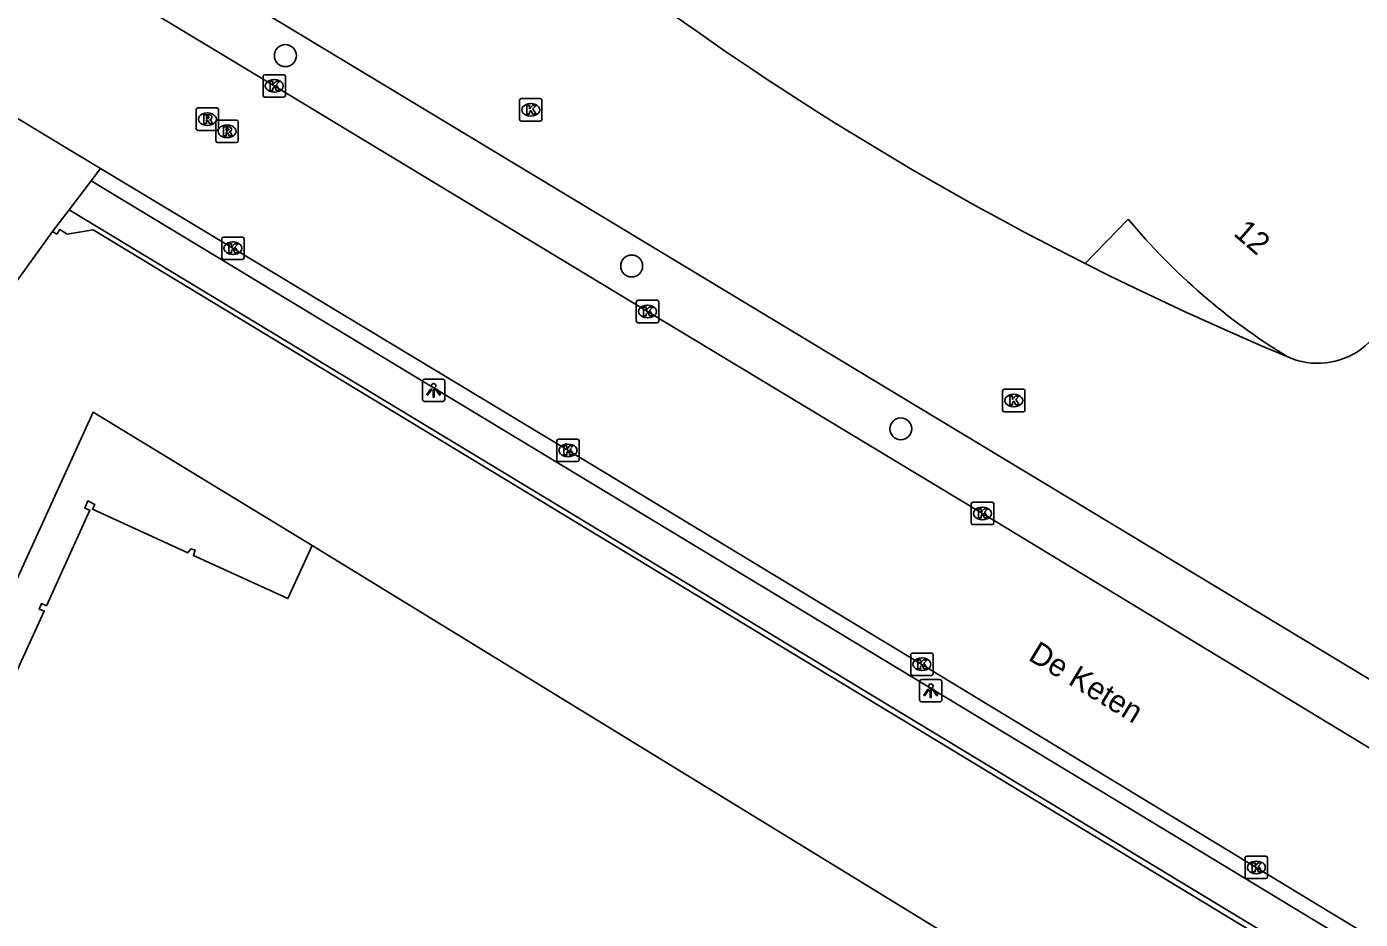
# Model space of a CAD drawing. Extents: x 156141 to 158132, y 385651 to 388399.
# Drawn here: x 156406.3 to 156465.9, y 386691.9 to 386731.7 of the extents above; entities that cross this region are included whole.
import ezdxf

# ---------------------------------------------------------------- set-up
doc = ezdxf.new("R2010")
doc.units = 0
for name, color, linetype in [('IMGEO_Berm_groen', 7, 'Continuous'), ('IMGEO_Boom', 7, 'Continuous'), ('IMGEO_Groenvoorziening', 7, 'Continuous'), ('IMGEO_Hek', 7, 'Continuous'), ('IMGEO_Kolk', 7, 'Continuous'), ('IMGEO_Lichtpunt', 7, 'Continuous'), ('IMGEO_Openbare_ruimte_label', 7, 'Continuous'), ('IMGEO_Pand', 7, 'Continuous'), ('IMGEO_Pand_nummerreeks', 7, 'Continuous'), ('IMGEO_Pand_overbouw', 7, 'Continuous'), ('IMGEO_Rijbaan_lokaal_gesloten', 7, 'Continuous'), ('IMGEO_Rijbaan_lokaal_open', 7, 'Continuous'), ('IMGEO_Rioolput', 7, 'Continuous'), ('IMGEO_Voetpad_open', 7, 'Continuous')]:
    doc.layers.add(name, color=color, linetype=linetype)

msp = doc.modelspace()

# ---------------------------------------------------------------- linework, layer by layer
at = {"layer": 'IMGEO_Berm_groen'}
msp.add_lwpolyline([(156478.507, 386695.242), (156416.672, 386732.53)], dxfattribs=at)
at = {"layer": 'IMGEO_Boom'}
for centre in [(156417.896, 386730.437), (156433.358, 386721.045), (156445.376, 386713.777)]:
    msp.add_circle(centre, 0.489, dxfattribs=at)
at = {"layer": 'IMGEO_Groenvoorziening'}
msp.add_lwpolyline([(156503.694, 386665.403), (156495.572, 386670.446), (156409.308, 386722.659), (156408.147, 386722.464), (156407.83, 386722.679), (156407.689, 386722.471), (156407.499, 386722.585)], dxfattribs=at)
at = {"layer": 'IMGEO_Hek'}
msp.add_lwpolyline([(156416.672, 386732.53), (156478.507, 386695.242)], dxfattribs=at)
at = {"layer": 'IMGEO_Kolk'}
for p, q in [((156416.899, 386728.659), (156416.899, 386729.511)), ((156416.974, 386729.585), (156417.826, 386729.585)), ((156417.387, 386729.365), (156417.412, 386729.365)), ((156417.9, 386729.511), (156417.9, 386728.659)), ((156417.41, 386728.805), (156417.385, 386728.805)), ((156417.826, 386728.585), (156416.974, 386728.585)), ((156428.352, 386727.59), (156428.352, 386728.442)), ((156428.427, 386728.516), (156429.279, 386728.516)), ((156428.84, 386728.296), (156428.865, 386728.296)), ((156429.353, 386728.442), (156429.353, 386727.59)), ((156429.279, 386727.516), (156428.427, 386727.516)), ((156428.863, 386727.736), (156428.838, 386727.736)), ((156415.051, 386721.413), (156415.051, 386722.265)), ((156415.126, 386722.339), (156415.978, 386722.339)), ((156415.539, 386722.119), (156415.564, 386722.119)), ((156416.052, 386722.265), (156416.052, 386721.413)), ((156415.562, 386721.559), (156415.537, 386721.559)), ((156415.978, 386721.339), (156415.126, 386721.339)), ((156433.567, 386718.589), (156433.567, 386719.441)), ((156433.642, 386719.515), (156434.494, 386719.515)), ((156434.055, 386719.295), (156434.08, 386719.295)), ((156434.568, 386719.441), (156434.568, 386718.589)), ((156434.494, 386718.515), (156433.642, 386718.515)), ((156434.078, 386718.735), (156434.053, 386718.735)), ((156449.997, 386715.541), (156450.849, 386715.541)), ((156449.922, 386714.615), (156449.922, 386715.467)), ((156450.41, 386715.321), (156450.435, 386715.321)), ((156450.923, 386715.467), (156450.923, 386714.615)), ((156450.849, 386714.541), (156449.997, 386714.541)), ((156450.433, 386714.761), (156450.408, 386714.761)), ((156430.015, 386712.389), (156430.015, 386713.241)), ((156430.09, 386713.315), (156430.942, 386713.315)), ((156431.016, 386713.241), (156431.016, 386712.389)), ((156430.526, 386712.535), (156430.501, 386712.535)), ((156430.503, 386713.095), (156430.528, 386713.095)), ((156430.942, 386712.315), (156430.09, 386712.315)), ((156448.524, 386709.575), (156448.524, 386710.427)), ((156448.599, 386710.501), (156449.451, 386710.501)), ((156449.012, 386710.281), (156449.037, 386710.281)), ((156449.525, 386710.427), (156449.525, 386709.575)), ((156449.035, 386709.721), (156449.01, 386709.721)), ((156449.451, 386709.501), (156448.599, 386709.501)), ((156445.818, 386702.843), (156445.818, 386703.695)), ((156445.893, 386703.769), (156446.745, 386703.769)), ((156446.819, 386703.695), (156446.819, 386702.843)), ((156446.329, 386702.989), (156446.304, 386702.989)), ((156446.306, 386703.549), (156446.331, 386703.549)), ((156446.745, 386702.769), (156445.893, 386702.769)), ((156460.828, 386694.7), (156461.68, 386694.7)), ((156460.753, 386693.774), (156460.753, 386694.626)), ((156461.241, 386694.48), (156461.266, 386694.48)), ((156461.754, 386694.626), (156461.754, 386693.774)), ((156461.68, 386693.7), (156460.828, 386693.7)), ((156461.264, 386693.92), (156461.239, 386693.92))]:
    msp.add_line(p, q, dxfattribs=at)
for points in [[(156416.899, 386728.659), (156416.899, 386729.511)], [(156416.974, 386729.585), (156417.826, 386729.585)], [(156417.22, 386729.285), (156417.343, 386729.285), (156417.343, 386729.134), (156417.473, 386729.285), (156417.637, 386729.285), (156417.491, 386729.134), (156417.644, 386728.885), (156417.492, 386728.885), (156417.407, 386729.049), (156417.343, 386728.982), (156417.343, 386728.885), (156417.22, 386728.885), (156417.22, 386729.285)], [(156417.9, 386729.511), (156417.9, 386728.659)], [(156417.826, 386728.585), (156416.974, 386728.585)], [(156428.352, 386727.59), (156428.352, 386728.442)], [(156428.427, 386728.516), (156429.279, 386728.516)], [(156428.673, 386728.216), (156428.796, 386728.216), (156428.796, 386728.065), (156428.926, 386728.216), (156429.09, 386728.216), (156428.944, 386728.065), (156429.097, 386727.816), (156428.945, 386727.816), (156428.86, 386727.98), (156428.796, 386727.913), (156428.796, 386727.816), (156428.673, 386727.816), (156428.673, 386728.216)], [(156429.353, 386728.442), (156429.353, 386727.59)], [(156429.279, 386727.516), (156428.427, 386727.516)], [(156415.051, 386721.413), (156415.051, 386722.265)], [(156415.126, 386722.339), (156415.978, 386722.339)], [(156416.052, 386722.265), (156416.052, 386721.413)], [(156415.372, 386722.039), (156415.495, 386722.039), (156415.495, 386721.888), (156415.625, 386722.039), (156415.789, 386722.039), (156415.643, 386721.888), (156415.796, 386721.639), (156415.644, 386721.639), (156415.559, 386721.803), (156415.495, 386721.736), (156415.495, 386721.639), (156415.372, 386721.639), (156415.372, 386722.039)], [(156415.978, 386721.339), (156415.126, 386721.339)], [(156433.567, 386718.589), (156433.567, 386719.441)], [(156433.642, 386719.515), (156434.494, 386719.515)], [(156433.888, 386719.215), (156434.011, 386719.215), (156434.011, 386719.064), (156434.141, 386719.215), (156434.305, 386719.215), (156434.159, 386719.064), (156434.312, 386718.815), (156434.16, 386718.815), (156434.075, 386718.979), (156434.011, 386718.912), (156434.011, 386718.815), (156433.888, 386718.815), (156433.888, 386719.215)], [(156434.568, 386719.441), (156434.568, 386718.589)], [(156434.494, 386718.515), (156433.642, 386718.515)], [(156449.997, 386715.541), (156450.849, 386715.541)], [(156449.922, 386714.615), (156449.922, 386715.467)], [(156450.243, 386715.241), (156450.366, 386715.241), (156450.366, 386715.09), (156450.496, 386715.241), (156450.66, 386715.241), (156450.514, 386715.09), (156450.667, 386714.841), (156450.515, 386714.841), (156450.43, 386715.005), (156450.366, 386714.938), (156450.366, 386714.841), (156450.243, 386714.841), (156450.243, 386715.241)], [(156450.923, 386715.467), (156450.923, 386714.615)], [(156450.849, 386714.541), (156449.997, 386714.541)], [(156430.015, 386712.389), (156430.015, 386713.241)], [(156430.09, 386713.315), (156430.942, 386713.315)], [(156431.016, 386713.241), (156431.016, 386712.389)], [(156430.336, 386713.015), (156430.459, 386713.015), (156430.459, 386712.864), (156430.589, 386713.015), (156430.753, 386713.015), (156430.607, 386712.864), (156430.76, 386712.615), (156430.608, 386712.615), (156430.523, 386712.779), (156430.459, 386712.712), (156430.459, 386712.615), (156430.336, 386712.615), (156430.336, 386713.015)], [(156430.942, 386712.315), (156430.09, 386712.315)], [(156448.524, 386709.575), (156448.524, 386710.427)], [(156448.599, 386710.501), (156449.451, 386710.501)], [(156448.845, 386710.201), (156448.968, 386710.201), (156448.968, 386710.05), (156449.098, 386710.201), (156449.262, 386710.201), (156449.116, 386710.05), (156449.269, 386709.801), (156449.117, 386709.801), (156449.032, 386709.965), (156448.968, 386709.898), (156448.968, 386709.801), (156448.845, 386709.801), (156448.845, 386710.201)], [(156449.525, 386710.427), (156449.525, 386709.575)], [(156449.451, 386709.501), (156448.599, 386709.501)], [(156445.818, 386702.843), (156445.818, 386703.695)], [(156445.893, 386703.769), (156446.745, 386703.769)], [(156446.819, 386703.695), (156446.819, 386702.843)], [(156446.139, 386703.469), (156446.262, 386703.469), (156446.262, 386703.318), (156446.392, 386703.469), (156446.556, 386703.469), (156446.41, 386703.318), (156446.563, 386703.069), (156446.411, 386703.069), (156446.326, 386703.233), (156446.262, 386703.166), (156446.262, 386703.069), (156446.139, 386703.069), (156446.139, 386703.469)], [(156446.745, 386702.769), (156445.893, 386702.769)], [(156460.828, 386694.7), (156461.68, 386694.7)], [(156460.753, 386693.774), (156460.753, 386694.626)], [(156461.074, 386694.4), (156461.197, 386694.4), (156461.197, 386694.249), (156461.327, 386694.4), (156461.491, 386694.4), (156461.345, 386694.249), (156461.498, 386694), (156461.346, 386694), (156461.261, 386694.164), (156461.197, 386694.097), (156461.197, 386694), (156461.074, 386694), (156461.074, 386694.4)], [(156461.754, 386694.626), (156461.754, 386693.774)], [(156461.68, 386693.7), (156460.828, 386693.7)]]:
    msp.add_lwpolyline(points, dxfattribs=at)
for centre, start, end in [((156416.976, 386729.509), 91.55205, 178.44795), ((156416.976, 386729.509), 91.55205, 178.44795), ((156417.824, 386729.509), 1.55205, 88.44795), ((156417.824, 386729.509), 1.55205, 88.44795), ((156416.976, 386728.661), 181.55205, 268.44795), ((156416.976, 386728.661), 181.55205, 268.44795), ((156417.824, 386728.661), 271.55205, 358.44795), ((156417.824, 386728.661), 271.55205, 358.44795), ((156428.429, 386728.44), 91.55205, 178.44795), ((156428.429, 386728.44), 91.55205, 178.44795), ((156429.277, 386728.44), 1.55205, 88.44795), ((156429.277, 386728.44), 1.55205, 88.44795), ((156428.429, 386727.592), 181.55205, 268.44795), ((156428.429, 386727.592), 181.55205, 268.44795), ((156429.277, 386727.592), 271.55205, 358.44795), ((156429.277, 386727.592), 271.55205, 358.44795), ((156415.128, 386722.263), 91.55205, 178.44795), ((156415.128, 386722.263), 91.55205, 178.44795), ((156415.976, 386722.263), 1.55205, 88.44795), ((156415.976, 386722.263), 1.55205, 88.44795), ((156415.128, 386721.415), 181.55205, 268.44795), ((156415.128, 386721.415), 181.55205, 268.44795), ((156415.976, 386721.415), 271.55205, 358.44795), ((156415.976, 386721.415), 271.55205, 358.44795), ((156433.644, 386719.439), 91.55205, 178.44795), ((156433.644, 386719.439), 91.55205, 178.44795), ((156434.492, 386719.439), 1.55205, 88.44795), ((156434.492, 386719.439), 1.55205, 88.44795), ((156433.644, 386718.591), 181.55205, 268.44795), ((156433.644, 386718.591), 181.55205, 268.44795), ((156434.492, 386718.591), 271.55205, 358.44795), ((156434.492, 386718.591), 271.55205, 358.44795), ((156449.999, 386715.465), 91.55205, 178.44795), ((156449.999, 386715.465), 91.55205, 178.44795), ((156450.847, 386715.465), 1.55205, 88.44795), ((156450.847, 386715.465), 1.55205, 88.44795), ((156449.999, 386714.617), 181.55205, 268.44795), ((156449.999, 386714.617), 181.55205, 268.44795), ((156450.847, 386714.617), 271.55205, 358.44795), ((156450.847, 386714.617), 271.55205, 358.44795), ((156430.092, 386713.239), 91.55205, 178.44795), ((156430.092, 386713.239), 91.55205, 178.44795), ((156430.94, 386713.239), 1.55205, 88.44795), ((156430.94, 386713.239), 1.55205, 88.44795), ((156430.092, 386712.391), 181.55205, 268.44795), ((156430.092, 386712.391), 181.55205, 268.44795), ((156430.94, 386712.391), 271.55205, 358.44795), ((156430.94, 386712.391), 271.55205, 358.44795), ((156448.601, 386710.425), 91.55205, 178.44795), ((156448.601, 386710.425), 91.55205, 178.44795), ((156449.449, 386710.425), 1.55205, 88.44795), ((156449.449, 386710.425), 1.55205, 88.44795), ((156448.601, 386709.577), 181.55205, 268.44795), ((156448.601, 386709.577), 181.55205, 268.44795), ((156449.449, 386709.577), 271.55205, 358.44795), ((156449.449, 386709.577), 271.55205, 358.44795), ((156445.895, 386703.693), 91.55205, 178.44795), ((156445.895, 386703.693), 91.55205, 178.44795), ((156446.743, 386703.693), 1.55205, 88.44795), ((156446.743, 386703.693), 1.55205, 88.44795), ((156445.895, 386702.845), 181.55205, 268.44795), ((156445.895, 386702.845), 181.55205, 268.44795), ((156446.743, 386702.845), 271.55205, 358.44795), ((156446.743, 386702.845), 271.55205, 358.44795), ((156460.83, 386694.624), 91.55205, 178.44795), ((156460.83, 386694.624), 91.55205, 178.44795), ((156461.678, 386694.624), 1.55205, 88.44795), ((156461.678, 386694.624), 1.55205, 88.44795), ((156460.83, 386693.776), 181.55205, 268.44795), ((156460.83, 386693.776), 181.55205, 268.44795), ((156461.678, 386693.776), 271.55205, 358.44795), ((156461.678, 386693.776), 271.55205, 358.44795)]:
    msp.add_arc(centre, 0.0765, start, end, dxfattribs=at)
for centre, major_axis, ratio, start_param, end_param in [((156417.386, 386729.085), (-0.387, 0.002), 0.722429, 4.712389, 7.853982), ((156417.411, 386729.085), (-0.39, 0.002), 0.717154, 1.570796, 4.712389), ((156428.839, 386728.016), (-0.387, 0.002), 0.722429, 4.712389, 7.853982), ((156428.864, 386728.016), (-0.39, 0.002), 0.717154, 1.570796, 4.712389), ((156415.538, 386721.839), (-0.387, 0.002), 0.722429, 4.712389, 7.853982), ((156415.563, 386721.839), (-0.39, 0.002), 0.717154, 1.570796, 4.712389), ((156434.054, 386719.015), (-0.387, 0.002), 0.722429, 4.712389, 7.853982), ((156434.079, 386719.015), (-0.39, 0.002), 0.717154, 1.570796, 4.712389), ((156450.409, 386715.041), (-0.387, 0.002), 0.722429, 4.712389, 7.853982), ((156450.434, 386715.041), (-0.39, 0.002), 0.717154, 1.570796, 4.712389), ((156430.502, 386712.815), (-0.387, 0.002), 0.722429, 4.712389, 7.853982), ((156430.527, 386712.815), (-0.39, 0.002), 0.717154, 1.570796, 4.712389), ((156449.011, 386710.001), (-0.387, 0.002), 0.722429, 4.712389, 7.853982), ((156449.036, 386710.001), (-0.39, 0.002), 0.717154, 1.570796, 4.712389), ((156446.305, 386703.269), (-0.387, 0.002), 0.722429, 4.712389, 7.853982), ((156446.33, 386703.269), (-0.39, 0.002), 0.717154, 1.570796, 4.712389), ((156461.24, 386694.2), (-0.387, 0.002), 0.722429, 4.712389, 7.853982), ((156461.265, 386694.2), (-0.39, 0.002), 0.717154, 1.570796, 4.712389)]:
    msp.add_ellipse(centre, major_axis=major_axis, ratio=ratio, start_param=start_param, end_param=end_param, dxfattribs=at)
at = {"layer": 'IMGEO_Lichtpunt'}
for p, q in [((156424.018, 386715.903), (156424.018, 386715.096)), ((156424.018, 386715.903), (156424.018, 386715.096)), ((156424.92, 386715.998), (156424.112, 386715.998)), ((156424.92, 386715.998), (156424.112, 386715.998)), ((156425.014, 386715.096), (156425.014, 386715.903)), ((156425.014, 386715.096), (156425.014, 386715.903)), ((156424.112, 386715.002), (156424.92, 386715.002)), ((156424.112, 386715.002), (156424.92, 386715.002)), ((156446.217, 386702.492), (156446.217, 386701.685)), ((156446.217, 386702.492), (156446.217, 386701.685)), ((156447.119, 386702.587), (156446.311, 386702.587)), ((156447.119, 386702.587), (156446.311, 386702.587)), ((156447.213, 386701.685), (156447.213, 386702.492)), ((156447.213, 386701.685), (156447.213, 386702.492)), ((156446.311, 386701.591), (156447.119, 386701.591)), ((156446.311, 386701.591), (156447.119, 386701.591))]:
    msp.add_line(p, q, dxfattribs=at)
for points in [[(156424.392, 386715.567), (156424.431, 386715.539), (156424.243, 386715.277), (156424.205, 386715.304), (156424.392, 386715.567)], [(156424.494, 386715.519), (156424.541, 386715.519), (156424.541, 386715.197), (156424.494, 386715.197), (156424.494, 386715.519)], [(156424.604, 386715.539), (156424.642, 386715.566), (156424.829, 386715.304), (156424.79, 386715.276), (156424.604, 386715.539)], [(156446.591, 386702.156), (156446.63, 386702.128), (156446.442, 386701.866), (156446.404, 386701.893), (156446.591, 386702.156)], [(156446.693, 386702.108), (156446.74, 386702.108), (156446.74, 386701.786), (156446.693, 386701.786), (156446.693, 386702.108)], [(156446.803, 386702.128), (156446.841, 386702.155), (156447.028, 386701.893), (156446.989, 386701.865), (156446.803, 386702.128)]]:
    msp.add_lwpolyline(points, dxfattribs=at)
for centre in [(156424.517, 386715.701), (156446.716, 386702.29)]:
    msp.add_circle(centre, 0.0994, dxfattribs=at)
for centre, start, end in [((156424.112, 386715.903), 90, 180), ((156424.112, 386715.903), 90, 180), ((156424.92, 386715.903), 0, 90), ((156424.92, 386715.903), 0, 90), ((156424.112, 386715.096), 180, 270), ((156424.112, 386715.096), 180, 270), ((156424.92, 386715.096), 270, 0), ((156424.92, 386715.096), 270, 360), ((156446.311, 386702.492), 90, 180), ((156446.311, 386702.492), 90, 180), ((156447.119, 386702.492), 0, 90), ((156447.119, 386702.492), 0, 90), ((156446.311, 386701.685), 180, 270), ((156446.311, 386701.685), 180, 270), ((156447.119, 386701.685), 270, 0), ((156447.119, 386701.685), 270, 360)]:
    msp.add_arc(centre, 0.0946, start, end, dxfattribs=at)
at = {"layer": 'IMGEO_Pand'}
for points in [[(156455.535, 386723.134), (156453.609, 386721.155)], [(156465.495, 386640.541), (156479.132, 386670.443), (156470.076, 386674.573), (156451.836, 386682.892), (156453.812, 386687.187), (156453.855, 386687.281), (156419.088, 386708.57), (156418.009, 386706.197), (156413.793, 386708.126), (156413.865, 386708.355), (156413.668, 386708.417), (156413.537, 386708.238), (156409.277, 386710.19), (156409.386, 386710.404), (156409.08, 386710.559), (156408.939, 386710.241), (156409.159, 386710.144), (156407.228, 386705.877), (156407.003, 386705.978), (156406.904, 386705.733), (156407.127, 386705.643), (156405.159, 386701.334)]]:
    msp.add_lwpolyline(points, dxfattribs=at)
for centre, radius, start, end in [((156516.446, 386846.045), 139.807, 233.4766, 243.29114), ((156477.474, 386741.349), 28.515, 219.70121, 238.70004), ((156463.993, 386719.976), 3.275, 245.98656, 7.19903)]:
    msp.add_arc(centre, radius, start, end, dxfattribs=at)
at = {"layer": 'IMGEO_Pand_overbouw'}
for points in [[(156455.535, 386723.134), (156453.609, 386721.155), (156454.724, 386720.599), (156455.844, 386720.052), (156456.968, 386719.516), (156458.098, 386718.989), (156459.232, 386718.473), (156460.37, 386717.967), (156461.513, 386717.47), (156462.66, 386716.984)], [(156405.159, 386701.334), (156407.127, 386705.643), (156406.904, 386705.733), (156407.003, 386705.978), (156407.228, 386705.877), (156409.159, 386710.144), (156408.939, 386710.241), (156409.08, 386710.559), (156409.386, 386710.404), (156409.277, 386710.19), (156413.537, 386708.238), (156413.668, 386708.417), (156413.865, 386708.355), (156413.793, 386708.126), (156418.009, 386706.197), (156419.088, 386708.57), (156409.309, 386714.517), (156399.301, 386692.603)]]:
    msp.add_lwpolyline(points, dxfattribs=at)
msp.add_arc((156477.474, 386741.349), 28.515, 219.70121, 238.70004, dxfattribs=at)
at = {"layer": 'IMGEO_Rijbaan_lokaal_gesloten'}
for points in [[(156475.759, 386693.817), (156466.52, 386699.403), (156449.019, 386710.003), (156434.062, 386719.017), (156417.394, 386729.087), (156414.135, 386731.05), (156411.519, 386732.626), (156409.811, 386733.655), (156406.482, 386735.661)], [(156401.627, 386730.006), (156401.716, 386730.169), (156401.957, 386730.031), (156405.455, 386727.922), (156407.166, 386726.89), (156409.646, 386725.395)], [(156409.646, 386725.395), (156415.548, 386721.836), (156430.513, 386712.82), (156446.317, 386703.253), (156461.249, 386694.203), (156479.607, 386683.066), (156496.242, 386672.993), (156500, 386670.722), (156503.944, 386668.339)]]:
    msp.add_lwpolyline(points, dxfattribs=at)
at = {"layer": 'IMGEO_Rijbaan_lokaal_open'}
for points in [[(156409.226, 386724.845), (156409.646, 386725.395)], [(156408.241, 386723.557), (156409.226, 386724.845)], [(156407.499, 386722.585), (156408.241, 386723.557)], [(156403.962, 386718.502), (156404.388, 386718.284), (156407.499, 386722.585)]]:
    msp.add_lwpolyline(points, dxfattribs=at)
at = {"layer": 'IMGEO_Rioolput'}
for p, q in [((156413.912, 386727.173), (156413.912, 386728.025)), ((156413.987, 386728.099), (156414.839, 386728.099)), ((156414.913, 386728.025), (156414.913, 386727.173)), ((156414.4, 386727.879), (156414.425, 386727.879)), ((156414.791, 386726.632), (156414.791, 386727.484)), ((156414.866, 386727.558), (156415.718, 386727.558)), ((156415.792, 386727.484), (156415.792, 386726.632)), ((156414.839, 386727.099), (156413.987, 386727.099)), ((156414.423, 386727.319), (156414.398, 386727.319)), ((156415.279, 386727.338), (156415.304, 386727.338)), ((156415.718, 386726.558), (156414.866, 386726.558)), ((156415.302, 386726.778), (156415.277, 386726.778))]:
    msp.add_line(p, q, dxfattribs=at)
for points in [[(156413.912, 386727.173), (156413.912, 386728.025)], [(156413.987, 386728.099), (156414.839, 386728.099)], [(156414.913, 386728.025), (156414.913, 386727.173)], [(156414.501, 386727.797), (156414.249, 386727.799), (156414.249, 386727.399)], [(156414.249, 386727.399), (156414.373, 386727.399), (156414.373, 386727.561), (156414.384, 386727.561)], [(156414.427, 386727.718), (156414.373, 386727.718), (156414.373, 386727.637)], [(156414.373, 386727.637), (156414.425, 386727.637)], [(156414.431, 386727.532), (156414.502, 386727.399), (156414.642, 386727.399), (156414.577, 386727.525)], [(156414.791, 386726.632), (156414.791, 386727.484)], [(156414.866, 386727.558), (156415.718, 386727.558)], [(156415.792, 386727.484), (156415.792, 386726.632)], [(156414.839, 386727.099), (156413.987, 386727.099)], [(156415.38, 386727.256), (156415.128, 386727.258), (156415.128, 386726.858)], [(156415.128, 386726.858), (156415.252, 386726.858), (156415.252, 386727.02), (156415.263, 386727.02)], [(156415.306, 386727.177), (156415.252, 386727.177), (156415.252, 386727.096)], [(156415.252, 386727.096), (156415.304, 386727.096)], [(156415.31, 386726.991), (156415.381, 386726.858), (156415.521, 386726.858), (156415.456, 386726.984)], [(156415.718, 386726.558), (156414.866, 386726.558)]]:
    msp.add_lwpolyline(points, dxfattribs=at)
for centre, radius, start, end in [((156413.989, 386728.023), 0.0765, 91.55205, 178.44795), ((156413.989, 386728.023), 0.0765, 91.55205, 178.44795), ((156414.837, 386728.023), 0.0765, 1.55205, 88.44795), ((156414.837, 386728.023), 0.0765, 1.55205, 88.44795), ((156414.383, 386727.508), 0.0533, 26.02933, 88.69889), ((156414.409, 386727.826), 0.19, 274.7715, 282.96867), ((156414.433, 386727.622), 0.0964, 77.00612, 93.18647), ((156414.447, 386727.679), 0.0378, 276.66336, 79.67722), ((156414.5, 386727.687), 0.109, 350.36119, 89.41601), ((156414.498, 386727.687), 0.112, 277.58423, 350.98172), ((156414.482, 386727.472), 0.108, 29.51342, 73.79051), ((156414.868, 386727.482), 0.0765, 91.55205, 178.44795), ((156414.868, 386727.482), 0.0765, 91.55205, 178.44795), ((156415.716, 386727.482), 0.0765, 1.55205, 88.44795), ((156415.716, 386727.482), 0.0765, 1.55205, 88.44795), ((156413.989, 386727.175), 0.0765, 181.55205, 268.44795), ((156413.989, 386727.175), 0.0765, 181.55205, 268.44795), ((156414.837, 386727.175), 0.0765, 271.55205, 358.44795), ((156414.837, 386727.175), 0.0765, 271.55205, 358.44795), ((156415.262, 386726.967), 0.0533, 26.02933, 88.69889), ((156415.288, 386727.285), 0.19, 274.7715, 282.96867), ((156415.312, 386727.081), 0.0964, 77.00612, 93.18647), ((156415.326, 386727.138), 0.0378, 276.66336, 79.67722), ((156415.379, 386727.146), 0.109, 350.36119, 89.41601), ((156415.377, 386727.146), 0.112, 277.58423, 350.98172), ((156415.361, 386726.931), 0.108, 29.51342, 73.79051), ((156414.868, 386726.634), 0.0765, 181.55205, 268.44795), ((156414.868, 386726.634), 0.0765, 181.55205, 268.44795), ((156415.716, 386726.634), 0.0765, 271.55205, 358.44795), ((156415.716, 386726.634), 0.0765, 271.55205, 358.44795)]:
    msp.add_arc(centre, radius, start, end, dxfattribs=at)
for centre, major_axis, ratio, start_param, end_param in [((156414.399, 386727.599), (-0.387, 0.002), 0.722429, 4.712389, 7.853982), ((156414.424, 386727.599), (-0.39, 0.002), 0.717154, 1.570796, 4.712389), ((156415.278, 386727.058), (-0.387, 0.002), 0.722429, 4.712389, 7.853982), ((156415.303, 386727.058), (-0.39, 0.002), 0.717154, 1.570796, 4.712389)]:
    msp.add_ellipse(centre, major_axis=major_axis, ratio=ratio, start_param=start_param, end_param=end_param, dxfattribs=at)
at = {"layer": 'IMGEO_Voetpad_open'}
for points in [[(156409.226, 386724.845), (156455.501, 386696.883), (156500, 386669.946), (156503.819, 386667.634)], [(156408.241, 386723.557), (156454.55, 386695.56), (156500, 386668.048), (156503.716, 386665.798)]]:
    msp.add_lwpolyline(points, dxfattribs=at)

# ---------------------------------------------------------------- texts
at = {"layer": 'IMGEO_Openbare_ruimte_label'}
msp.add_text('De Keten', height=1, rotation=328.79051, dxfattribs=at).set_placement((156451.02, 386703.489))
at = {"layer": 'IMGEO_Pand_nummerreeks'}
msp.add_text('12', height=1, rotation=319.20128, dxfattribs=at).set_placement((156460.185, 386722.449))

doc.saveas('drawing.dxf')
